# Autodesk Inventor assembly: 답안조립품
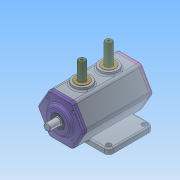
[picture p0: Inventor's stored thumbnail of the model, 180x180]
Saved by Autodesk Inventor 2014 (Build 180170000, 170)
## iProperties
Created: 2021-06
Part Number: 답안조립품
Document SubType Name: Assembly
Designer: net
Author: net
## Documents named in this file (11)
- C:\Users\net\Desktop\710606V1002\답안조립품.iam
- C:\Users\net\Desktop\710606V1002\답안부품.ipt
- C:\Users\net\Desktop\710606V1002\뒷커버.ipt
- C:\Users\net\Desktop\710606V1002\앞커버.ipt
- C:\Users\net\Desktop\710606V1002\베어링 6203.ipt
- C:\Users\net\Desktop\710606V1002\베어링 6302.ipt
- C:\Users\net\Desktop\710606V1002\부시.ipt
- C:\Users\net\Desktop\710606V1002\슬라이더.ipt
- C:\Users\net\Desktop\710606V1002\오일실.ipt
- C:\Users\net\Desktop\710606V1002\편심축.ipt
- C:\Users\net\Desktop\710606V1002\볼트 M4.ipt
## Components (10 placed, 3 different names)
1. 7-베어링 6203:1
2. 8-오일실:1
3. 9-M4-소켓머리:1
4. 9-M4-소켓머리:2
5. 9-M4-소켓머리:3
6. 9-M4-소켓머리:4
7. 9-M4-소켓머리:5
8. 9-M4-소켓머리:6
9. 9-M4-소켓머리:7
10. 9-M4-소켓머리:8
